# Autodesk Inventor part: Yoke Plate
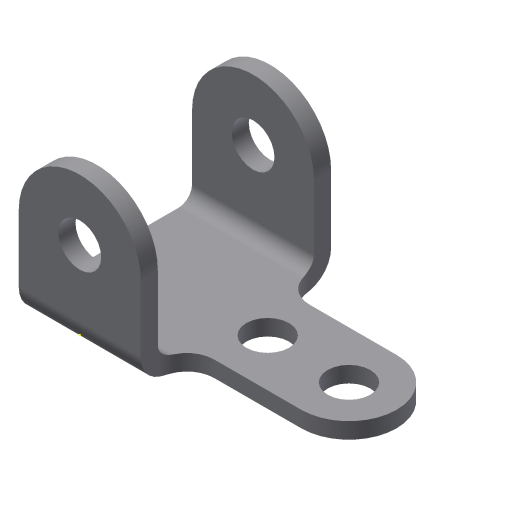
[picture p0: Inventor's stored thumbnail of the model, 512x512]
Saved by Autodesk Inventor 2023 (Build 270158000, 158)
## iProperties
Created: 2011-04
Part Number: Yoke Plate
Material: Generic
Document SubType Name: Modeling
Designer: Dell
Density: 1 g/cm^3
Appearance: Default
Author: Dell
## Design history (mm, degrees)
sketch "Sketch1"
  geometry: 1 further point
sketch "Sketch2"
  geometry: L1 (28.5, 36.5)-(28.5, -7.5); L2 (-28.5, -7.5)-(28.5, -7.5); L3 (-28.5, 36.5)-(-28.5, -7.5); C1 r 10 at (0, 36.5); A1 r 28.5 centre (0, 36.5) between (28.5, 36.5) and (-28.5, 36.5); 2 further points
  constraints: 6 end point, 2 centre point, 2 point on circle, 2 tangent, 2 vertical, 1 coincident, 1 perpendicular, 1 other
  dimensions: "d0" = 57 distance of L2.start L1.end; "d1" = 36.5 distance of point (0, 0) C1.centre; "d2" = 28.5 distance from line of L1 point (0, 0); "d3" = 20 diameter of C1; "d24" = 7.5 distance from line of point (0, 0) L2
extrude "Extrusion1" new body sketch "Sketch2" distance "d4" = 89; taper "d5" = 0 deg
sketch "Sketch3"
  geometry: L1 (44, 89)-(0, 89) reference; L2 (-28.588, 8)-(36.5, 8); L3 (36.5, 8)-(36.5, 81); L4 (36.5, 81)-(-28.588, 81); L5 (-28.588, 8)-(-28.588, 81); L6 (-28.5, 89)-(0, 89) reference; 3 further points
  constraints: 8 end point, 1 perpendicular
  dimensions: "d6" = 73 distance of L2.start L4.end; "d9" = 8 distance between parallel lines of L1 L4
extrude "Extrusion2" cut sketch "Sketch3" distance "d10" = 89; taper "d11" = 0 deg
sketch "Sketch4"
  geometry: L1 (0, 58.08)-(53.5, 58.08); L2 (53.5, 13.58)-(0, 13.58); L3 (0, 13.58)-(0, 58.08); L4 (0, 35.83)-(93.365, 35.83); L5 (0, 73)-(0, 0) reference; C1 r 10 at (53.5, 35.83); C2 r 10 at (15.5, 35.83); A1 r 22.25 centre (53.5, 35.83) between (53.5, 13.58) and (53.5, 58.08); 1 further point
  constraints: 8 end point, 3 centre point, 2 horizontal, 2 point on circle, 1 coincident, 1 collinear, 1 equal radius, 1 horizontal alignment, 1 parallel, 1 perpendicular, 1 point on line, 1 tangent
  dimensions: "d12" = 44.5 diameter of A1; "d13" = 44.5 distance between parallel lines of L2 L1; "d14" = 20 diameter of C1; "d15" = 38 distance of A1.centre C2.centre; "d23" = 15.5 distance from line of C2.centre L3
extrude "Extrusion3" join sketch "Sketch4" stored distance "d16" = 89; taper "d17" = 0 deg
fillet "Fillet1" dims "d18" = 12.7
fillet "Fillet2" dims "d19" = 6.35
fillet "Fillet3" dims "d20" = 12.75
body "Solid1"
